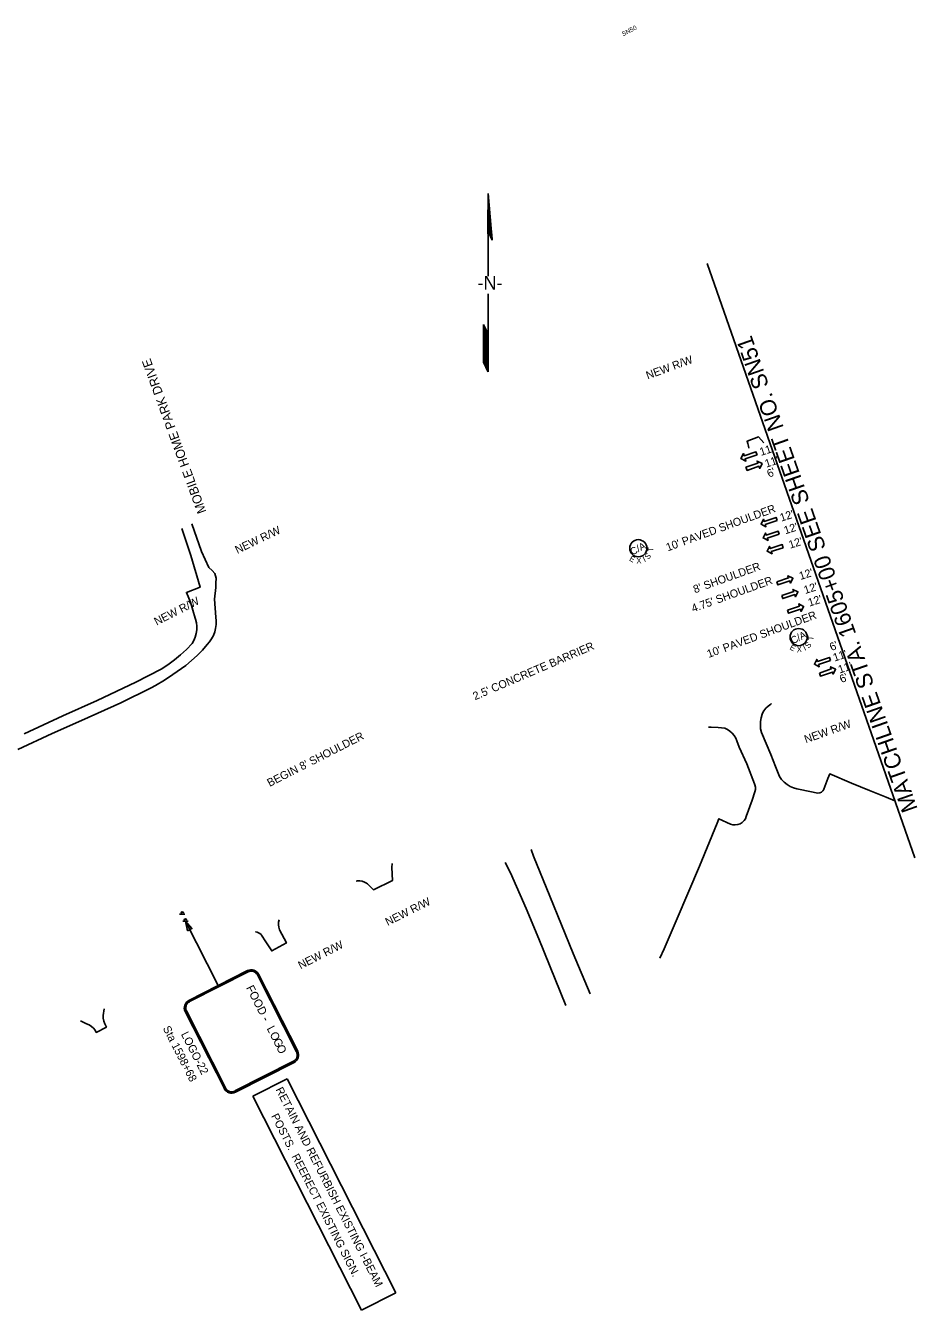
# Model space of a CAD drawing. Extents: x 1806030 to 1807588, y 1188872 to 1190302.
# Drawn here: x 1806809 to 1807588, y 1189179 to 1190302 of the extents above; entities that cross this region are included whole.
import ezdxf

# ---------------------------------------------------------------- set-up
doc = ezdxf.new("R2010")
doc.units = 0
for name, color, linetype in [('RD_EX_Road', 7, 'Continuous'), ('RD_PD_Final_LnLine', 7, 'Continuous'), ('RD_PD_Final_TX', 7, 'Continuous'), ('RD_PD_RW_TX', 7, 'Continuous'), ('RD_SHT_MatchLine', 7, 'Continuous'), ('RD_SHT_TX', 7, 'Continuous'), ('RD_Sketch1', 7, 'Continuous'), ('RD_Sketch8', 7, 'Continuous'), ('RD_TX_RoadID', 7, 'Continuous'), ('SN_P_Signs', 7, 'Continuous')]:
    doc.layers.add(name, color=color, linetype=linetype)

# ---------------------------------------------------------------- blocks, each defined once
blk = doc.blocks.new('SARRW2')
at = {"layer": 'RD_PD_Final_LnLine'}
blk.add_lwpolyline([(-12, 1.2), (-12, -1.2), (-2.83, -1.2), (-2.83, -2.83), (0, 0), (-2.83, 2.83), (-2.83, 1.2)], close=True, dxfattribs=at)

msp = doc.modelspace()

# ---------------------------------------------------------------- linework, layer by layer
at = {"layer": 'RD_EX_Road'}
for points in [[(1807454.1, 1189937.2), (1807449.7, 1189942.4), (1807439.6, 1189938.6), (1807440.3, 1189936.6), (1807440.8, 1189934.4), (1807441.1, 1189932.6)], [(1806954.1, 1189866.4), (1806962.7, 1189842.1), (1806969, 1189828.3), (1806972, 1189825.5), (1806974.2, 1189823), (1806975.4, 1189818.7), (1806975.3, 1189814.6), (1806975.3, 1189810.7), (1806974.1, 1189800.6), (1806975.1, 1189784.7), (1806975.5, 1189781.5), (1806975.5, 1189778.2), (1806975, 1189774.9), (1806974.2, 1189771.8), (1806973, 1189768.7), (1806971.5, 1189765.8), (1806969.6, 1189763.1), (1806967.6, 1189760.9), (1806963.4, 1189755.9), (1806958.8, 1189751.2), (1806953.9, 1189746.7), (1806948.8, 1189742.5), (1806945, 1189739.7), (1806937.7, 1189734.5), (1806930.2, 1189729.6), (1806922.5, 1189725.1), (1806918.6, 1189722.9), (1806892.1, 1189709.8), (1806857.7, 1189694.3), (1806832.1, 1189683), (1806802, 1189669.1)], [(1806945.3, 1189862.2), (1806953.2, 1189838.7), (1806961.4, 1189810.9), (1806949.4, 1189806.4), (1806952.9, 1189797.9), (1806957.1, 1189783.9), (1806957.4, 1189783), (1806958.2, 1189779.9), (1806958.5, 1189776.8), (1806958.5, 1189773.6), (1806958, 1189770.4), (1806957.2, 1189767.3), (1806956, 1189764.4), (1806954.4, 1189761.6), (1806954.4, 1189761.6), (1806949.5, 1189756.5), (1806944.3, 1189751.7), (1806938.9, 1189747.3), (1806933.2, 1189743.1), (1806927.4, 1189739.2), (1806905.2, 1189727.9), (1806871.3, 1189711.8), (1806841.4, 1189698.3), (1806807.7, 1189682.6)], [(1807460.9, 1189709.2), (1807460.2, 1189708.7), (1807458, 1189707), (1807456, 1189705), (1807454.3, 1189702.8), (1807452.9, 1189700.3), (1807452.8, 1189700), (1807451.9, 1189696.8), (1807451.3, 1189693.6), (1807451.2, 1189690.3), (1807451.4, 1189687.1), (1807452.1, 1189683.9), (1807460.2, 1189664.7), (1807464.3, 1189654), (1807467.9, 1189645.4), (1807469.8, 1189642.8), (1807472, 1189640.4), (1807474.5, 1189638.4), (1807477.2, 1189636.7), (1807480.2, 1189635.4), (1807483.2, 1189634.5), (1807486, 1189634), (1807501.4, 1189630.9), (1807503.1, 1189631), (1807504.7, 1189631.7), (1807505.9, 1189632.8), (1807506.7, 1189634.1), (1807506.8, 1189634.3), (1807510.2, 1189643.6), (1807511.9, 1189647.7), (1807530.9, 1189639.7), (1807546.5, 1189633.2), (1807561.2, 1189627.2), (1807568.7, 1189624)], [(1807405.8, 1189688.6), (1807408.3, 1189688.6), (1807414.2, 1189688.3), (1807420.1, 1189687.6), (1807422.4, 1189686.5), (1807424.6, 1189685.1), (1807426.5, 1189683.3), (1807428.2, 1189681.2), (1807429.6, 1189678.9), (1807430.5, 1189676.5), (1807432.8, 1189671.1), (1807439.3, 1189656.4), (1807446.1, 1189639.1), (1807446.4, 1189638.1), (1807446.8, 1189636.1), (1807446.8, 1189633.9), (1807446.3, 1189631.9), (1807443.9, 1189624.8), (1807438.8, 1189610.3), (1807438.1, 1189608.5), (1807436.9, 1189606.8), (1807435.4, 1189605.2), (1807433.5, 1189604.1), (1807431.5, 1189603.4), (1807429.3, 1189603.1), (1807427.2, 1189603.2), (1807425.2, 1189603.8), (1807415, 1189608.4), (1807413.3, 1189604.7), (1807398.1, 1189567.1), (1807378.5, 1189521.1), (1807367, 1189494.6), (1807363.2, 1189486.6)], [(1807302.3, 1189455.3), (1807287.6, 1189490.7), (1807267, 1189540.6), (1807252.9, 1189575.7), (1807250.8, 1189581.5)], [(1807097.8, 1189554), (1807098.9, 1189554.2), (1807101, 1189554.2), (1807103.1, 1189553.9), (1807105, 1189553.1), (1807106.8, 1189552), (1807107.6, 1189551.4), (1807113, 1189546.4), (1807129.5, 1189554.3), (1807129, 1189565.8), (1807129.2, 1189569.2)], [(1807228.2, 1189570.1), (1807232.7, 1189561.2), (1807246.4, 1189529.9), (1807257.4, 1189503.3), (1807271.7, 1189468.2), (1807281.2, 1189445.2)], [(1807009.9, 1189509.5), (1807009.9, 1189509.5), (1807011.2, 1189509.2), (1807012.5, 1189508.7), (1807013.6, 1189508), (1807014.7, 1189507.2), (1807015.1, 1189506.7), (1807018.9, 1189500.9), (1807024.1, 1189492.9), (1807036.9, 1189499.8), (1807030.7, 1189511.4), (1807030.1, 1189513.5), (1807029.9, 1189515.7), (1807030, 1189517.9), (1807030.6, 1189520), (1807030.6, 1189520)], [(1806856.8, 1189431.7), (1806862.2, 1189429.1), (1806864.4, 1189428.2), (1806866.4, 1189426.9), (1806868.1, 1189425.3), (1806869.6, 1189423.5), (1806870.6, 1189421.6), (1806879.5, 1189426.2), (1806878, 1189429), (1806877.2, 1189431.5), (1806876.8, 1189434), (1806876.8, 1189436.5), (1806877.5, 1189442.2)]]:
    msp.add_lwpolyline(points, dxfattribs=at)
at = {"layer": 'RD_SHT_MatchLine'}
msp.add_line((1807404.8, 1190094.1), (1807586.1, 1189574.2), dxfattribs=at)
at = {"layer": 'RD_Sketch1'}
for p, q in [((1807213.1, 1190155.1), (1807212.9, 1190119.9)), ((1807216.8, 1190114.4), (1807213.1, 1190155.1)), ((1807213.1, 1190120.2), (1807213.1, 1190098.4)), ((1807213.4, 1190121.3), (1807216.8, 1190114.4)), ((1807213.1, 1190098.4), (1807213.1, 1190082.9)), ((1807213.1, 1190067.5), (1807213.1, 1190041.7)), ((1807209.1, 1190026.6), (1807209.1, 1190040.8)), ((1807209.1, 1190040.8), (1807213.1, 1190032.2)), ((1807213.1, 1190041.7), (1807213.1, 1189999.2)), ((1807209.1, 1190007.7), (1807209.1, 1190026.6)), ((1807213.1, 1189999.2), (1807209.1, 1190007.7))]:
    msp.add_line(p, q, dxfattribs=at)
for points in [[(1807213.1, 1190120.5), (1807213.1, 1190155)], [(1807213.2, 1190120.8), (1807213.2, 1190153.9)], [(1807213.3, 1190121), (1807213.3, 1190152.9)], [(1807213.4, 1190121.3), (1807213.4, 1190151.9)], [(1807213.5, 1190121.1), (1807213.5, 1190150.8)], [(1807213.6, 1190121), (1807213.6, 1190149.8)], [(1807213.7, 1190120.8), (1807213.7, 1190148.8)], [(1807213, 1190120.3), (1807213, 1190141)], [(1807213.7, 1190120.6), (1807213.7, 1190147.7)], [(1807213.8, 1190120.4), (1807213.8, 1190146.7)], [(1807213.9, 1190120.2), (1807213.9, 1190145.7)], [(1807214, 1190120), (1807214, 1190144.6)], [(1807214.1, 1190119.8), (1807214.1, 1190143.6)], [(1807214.2, 1190119.6), (1807214.2, 1190142.6)], [(1807214.3, 1190119.4), (1807214.3, 1190141.5)], [(1807214.4, 1190119.2), (1807214.4, 1190140.5)], [(1807214.5, 1190119), (1807214.5, 1190139.5)], [(1807214.6, 1190118.8), (1807214.6, 1190138.4)], [(1807214.7, 1190118.7), (1807214.7, 1190137.4)], [(1807214.8, 1190118.5), (1807214.8, 1190136.4)], [(1807214.9, 1190118.3), (1807214.9, 1190135.3)], [(1807215, 1190118.1), (1807215, 1190134.3)], [(1807215.1, 1190117.9), (1807215.1, 1190133.3)], [(1807215.2, 1190117.7), (1807215.2, 1190132.2)], [(1807215.3, 1190117.5), (1807215.3, 1190131.2)], [(1807215.4, 1190117.3), (1807215.4, 1190130.2)], [(1807215.4, 1190117.1), (1807215.4, 1190129.1)], [(1807215.5, 1190116.9), (1807215.5, 1190128.1)], [(1807215.6, 1190116.7), (1807215.6, 1190127.1)], [(1807215.7, 1190116.5), (1807215.7, 1190126.1)], [(1807212.9, 1190120), (1807212.9, 1190125.1)], [(1807215.8, 1190116.4), (1807215.8, 1190125)], [(1807215.9, 1190116.2), (1807215.9, 1190124)], [(1807216, 1190116), (1807216, 1190123)], [(1807216.1, 1190115.8), (1807216.1, 1190121.9)], [(1807216.2, 1190115.6), (1807216.2, 1190120.9)], [(1807216.3, 1190115.4), (1807216.3, 1190119.9)], [(1807216.4, 1190115.2), (1807216.4, 1190118.8)], [(1807216.5, 1190115), (1807216.5, 1190117.8)], [(1807216.6, 1190114.8), (1807216.6, 1190116.8)], [(1807216.7, 1190114.6), (1807216.7, 1190115.7)], [(1807216.8, 1190114.4), (1807216.8, 1190114.7)], [(1807209.2, 1190007.6), (1807209.2, 1190040.6)], [(1807209.3, 1190007.4), (1807209.3, 1190040.4)], [(1807209.3, 1190007.2), (1807209.3, 1190040.2)], [(1807209.4, 1190007), (1807209.4, 1190040)], [(1807209.5, 1190006.8), (1807209.5, 1190039.8)], [(1807209.6, 1190006.6), (1807209.6, 1190039.6)], [(1807209.7, 1190006.4), (1807209.7, 1190039.4)], [(1807209.8, 1190006.2), (1807209.8, 1190039.2)], [(1807209.9, 1190006), (1807209.9, 1190039)], [(1807210, 1190005.8), (1807210, 1190038.8)], [(1807210.1, 1190005.6), (1807210.1, 1190038.6)], [(1807210.2, 1190005.3), (1807210.2, 1190038.4)], [(1807210.3, 1190005.1), (1807210.3, 1190038.2)], [(1807210.4, 1190004.9), (1807210.4, 1190038)], [(1807210.5, 1190004.7), (1807210.5, 1190037.8)], [(1807210.6, 1190004.5), (1807210.6, 1190037.6)], [(1807210.7, 1190004.3), (1807210.7, 1190037.4)], [(1807210.8, 1190004.1), (1807210.8, 1190037.2)], [(1807210.9, 1190003.9), (1807210.9, 1190037)], [(1807211, 1190003.7), (1807211, 1190036.8)], [(1807211, 1190003.5), (1807211, 1190036.6)], [(1807211.1, 1190003.3), (1807211.1, 1190036.4)], [(1807211.2, 1190003.1), (1807211.2, 1190036.2)], [(1807211.3, 1190002.9), (1807211.3, 1190036)], [(1807211.4, 1190002.7), (1807211.4, 1190035.8)], [(1807211.5, 1190002.5), (1807211.5, 1190035.6)], [(1807211.6, 1190002.3), (1807211.6, 1190035.4)], [(1807211.7, 1190002.1), (1807211.7, 1190035.2)], [(1807211.8, 1190001.9), (1807211.8, 1190035)], [(1807211.9, 1190001.7), (1807211.9, 1190034.8)], [(1807212, 1190001.5), (1807212, 1190034.6)], [(1807212.1, 1190001.3), (1807212.1, 1190034.4)], [(1807212.2, 1190001.1), (1807212.2, 1190034.2)], [(1807212.3, 1190000.9), (1807212.3, 1190034)], [(1807212.4, 1190000.7), (1807212.4, 1190033.8)], [(1807212.5, 1190000.5), (1807212.5, 1190033.6)], [(1807212.6, 1190000.3), (1807212.6, 1190033.4)], [(1807212.7, 1190000.1), (1807212.7, 1190033.1)], [(1807212.7, 1189999.9), (1807212.7, 1190032.9)], [(1807212.8, 1189999.7), (1807212.8, 1190032.7)], [(1807212.9, 1189999.5), (1807212.9, 1190032.5)], [(1807213, 1189999.3), (1807213, 1190032.3)]]:
    msp.add_lwpolyline(points, dxfattribs=at)
at = {"layer": 'RD_Sketch8'}
for centre in [(1807344.5, 1189845), (1807484.7, 1189767.3)]:
    msp.add_circle(centre, 7.5, dxfattribs=at)
at = {"layer": 'SN_P_Signs'}
for p, q in [((1806943.5, 1189525), (1806948, 1189525)), ((1806946.4, 1189518.8), (1806950.9, 1189518.8)), ((1806977.2, 1189462.6), (1806948.6, 1189518.8)), ((1807007.5, 1189365.8), (1807037.5, 1189381)), ((1807037.5, 1189381), (1807132.6, 1189193.8)), ((1807102.6, 1189178.6), (1807007.5, 1189365.8)), ((1807132.6, 1189193.8), (1807102.6, 1189178.6))]:
    msp.add_line(p, q, dxfattribs=at)
msp.add_lwpolyline([(1806950.5, 1189510.5), (1806948.6, 1189518.8), (1806954.2, 1189512.4)], close=True, dxfattribs=at)
for points in [[(1806951.5, 1189449.5), (1807002.8, 1189475.6)], [(1806952, 1189448.5), (1807003.4, 1189474.6)], [(1807011.5, 1189471.9), (1807045.7, 1189404.5)], [(1807012.5, 1189472.5), (1807046.8, 1189405.1)], [(1806983.6, 1189373), (1806949.4, 1189440.4)], [(1806982.6, 1189372.5), (1806948.3, 1189439.9)], [(1807043.1, 1189396.5), (1806991.7, 1189370.4)], [(1807043.6, 1189395.4), (1806992.3, 1189369.3)]]:
    msp.add_lwpolyline(points, dxfattribs=at)
for centre in [(1806945.8, 1189526), (1806948.6, 1189519.8)]:
    msp.add_circle(centre, 1, dxfattribs=at)
for centre, radius, start, end in [((1807006.1, 1189469.2), 7.2, 26.9317, 116.9317), ((1807006.1, 1189469.2), 6, 26.9317, 116.9317), ((1806954.8, 1189443.1), 7.2, 116.9317, 206.9317), ((1806954.8, 1189443.1), 6, 116.9317, 206.9317), ((1807040.3, 1189401.8), 6, 296.9317, 26.9317), ((1807040.3, 1189401.8), 7.2, 296.9317, 26.9317), ((1806989, 1189375.7), 6, 206.9317, 296.9317), ((1806989, 1189375.7), 7.2, 206.9317, 296.9317)]:
    msp.add_arc(centre, radius, start, end, dxfattribs=at)

# ---------------------------------------------------------------- block references
at = {"layer": 'RD_PD_Final_LnLine'}
for p, xscale, yscale, rotation in [((1807434.2, 1189923.4), 1.1999999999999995, 1.2000000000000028, -161.0852911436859), ((1807452.7, 1189919.1), 1.1999999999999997, 1.2000000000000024, 18.914708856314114), ((1807451.8, 1189866), 1.1999999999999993, 1.2000000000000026, -161.5277674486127), ((1807453.6, 1189854), 1.1999999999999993, 1.2000000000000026, -161.5277674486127), ((1807457.1, 1189842.3), 1.1999999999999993, 1.2000000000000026, -161.5277674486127), ((1807479.6, 1189818.8), 1.1999999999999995, 1.2000000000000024, 18.472232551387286), ((1807484, 1189806.9), 1.1999999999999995, 1.2000000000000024, 18.472232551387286), ((1807489, 1189794.1), 1.1999999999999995, 1.2000000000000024, 18.472232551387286), ((1807498.4, 1189743.5), 1.1999999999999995, 1.2000000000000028, -161.0852911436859), ((1807516.9, 1189739.2), 1.1999999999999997, 1.2000000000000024, 18.914708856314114)]:
    msp.add_blockref('SARRW2', p, dxfattribs=dict(at, xscale=xscale, yscale=yscale, rotation=rotation))

# ---------------------------------------------------------------- texts
at = {"layer": 'RD_PD_Final_TX'}
for s, rotation, p in [("11'", 18.2879, (1807451.8, 1189925.7)), ("11'", 18.2879, (1807456.4, 1189915.4)), ("6' ", 26.8178, (1807459.1, 1189906.5)), ("10' PAVED SHOULDER", 20.1096, (1807370.2, 1189842.2)), ("12'", 17.8454, (1807469.5, 1189868.2)), ("12'", 17.7678, (1807473, 1189857.1)), ("12'", 17.8454, (1807477.2, 1189844.5)), ("8' SHOULDER", 19.8814, (1807394, 1189805.5)), ("12'", 17.7678, (1807486.3, 1189817.2)), ("4.75' SHOULDER", 19.8814, (1807392.4, 1189788.8)), ("12'", 17.7678, (1807490.4, 1189804.9)), ("12'", 17.7678, (1807494.1, 1189793.9)), ("10' PAVED SHOULDER", 20.1574, (1807406, 1189749)), ("2.5' CONCRETE BARRIER", 23.2238, (1807201.7, 1189712)), ("6' ", 26.8178, (1807513.8, 1189754.9)), ("11'", 18.2879, (1807516, 1189745.8)), ("11'", 18.2879, (1807520.5, 1189735.4)), ("6' ", 26.8178, (1807522.5, 1189726.9)), ("BEGIN 8' SHOULDER", 27.034, (1807022.2, 1189636.2))]:
    msp.add_text(s, height=7, rotation=rotation, dxfattribs=at).set_placement(p)
at = {"layer": 'RD_PD_RW_TX'}
for rotation, p in [(20.0709, (1807352.7, 1189992.6)), (25.6269, (1806994, 1189840)), (26.8778, (1806923.4, 1189777.3)), (19.5242, (1807491, 1189674.4)), (26.5977, (1807125.4, 1189514.6)), (26.9299, (1807049.3, 1189476.7))]:
    msp.add_text('NEW R/W', height=7, rotation=rotation, dxfattribs=at).set_placement(p)
at = {"layer": 'RD_SHT_TX'}
for s, height, rotation, p in [('SN50', 4, 26.9317, (1807331.3, 1190292.7)), ('MATCHLINE STA. 1605+00 SEE SHEET NO. SN51', 14.173, 109.3446, (1807588.9, 1189617))]:
    msp.add_text(s, height=height, rotation=rotation, dxfattribs=at).set_placement(p)
at = {"layer": 'RD_Sketch1'}
msp.add_text('-N-', height=11.81, rotation=0, dxfattribs=at).set_placement((1807203.9, 1190071.2))
at = {"layer": 'RD_Sketch8'}
for s, height, rotation, p in [('C/A', 6.25, 26.9317, (1807339.3, 1189838.7)), ('T', 5, 85.1168, (1807357.5, 1189841.8)), ('E', 5, 330.1429, (1807336.1, 1189834.5)), ('X', 5, 2.5723, (1807342.9, 1189831.6)), ('I', 5, 26.7323, (1807349.9, 1189832.8)), ('S', 5, 48.7241, (1807353.1, 1189834.7)), ('C/A', 6.25, 26.9317, (1807479.6, 1189761)), ('T', 5, 85.1168, (1807497.7, 1189764.2)), ('E', 5, 330.1429, (1807476.3, 1189756.9)), ('X', 5, 2.5723, (1807483.1, 1189754)), ('I', 5, 26.7323, (1807490.1, 1189755.2)), ('S', 5, 48.7241, (1807493.3, 1189757))]:
    msp.add_text(s, height=height, rotation=rotation, dxfattribs=at).set_placement(p)
at = {"layer": 'RD_TX_RoadID'}
msp.add_text('MOBILE HOME PARK DRIVE', height=8, rotation=110.0351, dxfattribs=at).set_placement((1806966.9, 1189877))
at = {"layer": 'SN_P_Signs'}
for s, height, p in [('FOOD', 7.2, (1807001.4, 1189460.6)), ('-', 7.2, (1807015.2, 1189433.4)), ('-', 7.2, (1807015.2, 1189433.4)), ('Sta 1598+68', 7, (1806928.6, 1189425.2)), ('LOGO-22', 7, (1806944.5, 1189420.1)), ('L', 7.2, (1807019.4, 1189425.1)), ('L', 7.2, (1807019.4, 1189425.1)), ('O', 7.2, (1807022, 1189420)), ('O', 7.2, (1807022, 1189420)), ('G', 7.2, (1807024.9, 1189414.3)), ('G', 7.2, (1807024.9, 1189414.3)), ('O', 7.2, (1807027.7, 1189408.7)), ('O', 7.2, (1807027.7, 1189408.7)), ('RETAIN AND REFURBISH EXISTING I-BEAM', 7, (1807027.2, 1189371.6)), ('POSTS.  REERECT EXISTING SIGN.', 7, (1807023.3, 1189348.5))]:
    msp.add_text(s, height=height, rotation=296.9317, dxfattribs=at).set_placement(p)

doc.saveas('drawing.dxf')
